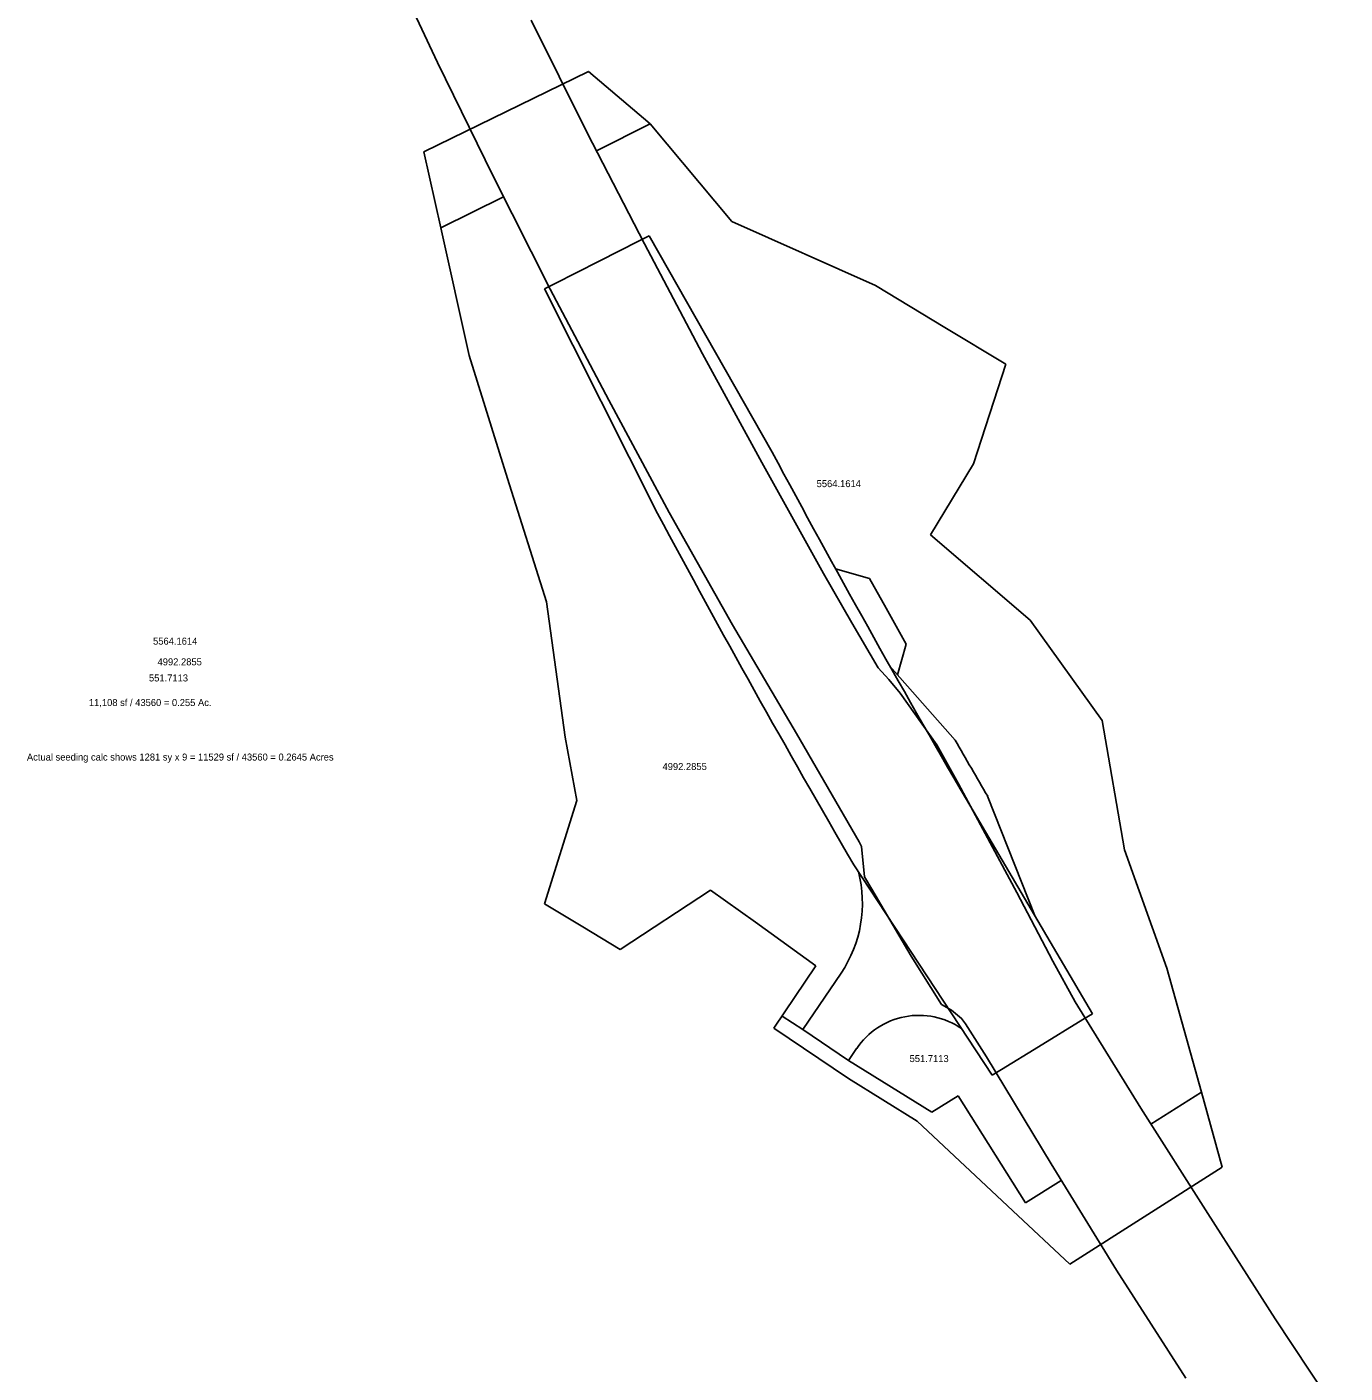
# Model space of a CAD drawing. Extents: x 2231639 to 2237084, y 681731 to 684172.
# Drawn here: x 2232533.2 to 2232796.6, y 683553.4 to 683822.5 of the extents above; entities that cross this region are included whole.
import ezdxf

# ---------------------------------------------------------------- set-up
doc = ezdxf.new("R2010")
doc.units = 0
for name, color, linetype in [('DT_P_Slope_Break_Line', 7, 'Continuous'), ('DT_X_Slope_Break_Line', 7, 'Continuous'), ('PV_P_Drive', 7, 'Continuous'), ('PV_P_Field_Drive', 7, 'Continuous'), ('PV_X_Shoulder_Aggregate', 7, 'Continuous'), ('RW_P_Const_Limits', 7, 'Continuous'), ('SH_Cut_Line', 7, 'Continuous'), ('SH_Named_Boundary', 7, 'Continuous'), ('VG_X_Cells', 7, 'Continuous')]:
    doc.layers.add(name, color=color, linetype=linetype)

msp = doc.modelspace()

# ---------------------------------------------------------------- linework, layer by layer
at = {"layer": 'DT_P_Slope_Break_Line'}
for p, q in [((2232684.08, 683624.78), (2232688.26, 683622.05)), ((2232697.39, 683615.9), (2232714.03, 683605.56)), ((2232719.31, 683608.8), (2232732.74, 683587.46))]:
    msp.add_line(p, q, dxfattribs=at)
at = {"layer": 'DT_X_Slope_Break_Line'}
for p, q in [((2232646.98, 683797.74), (2232657.72, 683803.08)), ((2232628.43, 683788.53), (2232615.86, 683782.29)), ((2232757.76, 683603.17), (2232767.89, 683609.53)), ((2232739.85, 683591.93), (2232732.74, 683587.46))]:
    msp.add_line(p, q, dxfattribs=at)
at = {"layer": 'PV_P_Drive'}
for p, q in [((2232718.66, 683679.94), (2232705.64, 683694.7)), ((2232725.17, 683668.69), (2232734.64, 683644.7)), ((2232695.88, 683633.36), (2232688.26, 683622.05)), ((2232697.39, 683615.9), (2232688.26, 683622.05)), ((2232698.99, 683618.29), (2232697.39, 683615.9))]:
    msp.add_line(p, q, dxfattribs=at)
for centre, radius, start, end in [((2234655.37, 684794.71), 2234.63, 209.92483, 210.25805), ((2232675.14, 683647.32), 25, 326.0548, 14.6337), ((2232711.44, 683609.91), 15, 55.5655, 146.0548)]:
    msp.add_arc(centre, radius, start, end, dxfattribs=at)
at = {"layer": 'PV_P_Field_Drive'}
for p, q in [((2232694.78, 683714.18), (2232701.55, 683712.24)), ((2232704.87, 683706.29), (2232701.55, 683712.24)), ((2232704.87, 683706.29), (2232708.89, 683699.08)), ((2232707.18, 683692.96), (2232708.89, 683699.08))]:
    msp.add_line(p, q, dxfattribs=at)
at = {"layer": 'PV_X_Shoulder_Aggregate'}
for points in [[(2232764.79, 683552.38), (2232750.93, 683574), (2232737.84, 683595.2), (2232724.91, 683616.61), (2232720.74, 683623.22), (2232719.95, 683624.29), (2232717.97, 683625.92), (2232715.97, 683627.1), (2232709.9, 683636.74), (2232702, 683650.15), (2232700.59, 683652.63), (2232699.93, 683658.67), (2232699.5, 683659.61), (2232686.97, 683681.28), (2232674.19, 683702.97), (2232661.51, 683725.43), (2232649.43, 683747.85), (2232637.74, 683770.04), (2232626.37, 683792.62), (2232615.25, 683815.35), (2232604.74, 683837.71)], [(2232796.61, 683543.1), (2232782.62, 683564.26), (2232769.18, 683585.29), (2232755.81, 683606.33), (2232742.64, 683627.63), (2232738.17, 683635.73), (2232731.01, 683649.47), (2232719.35, 683671.19), (2232715.01, 683678.98), (2232707.7, 683689.28), (2232705.39, 683692.01), (2232703.27, 683694.38), (2232698.03, 683703.34), (2232692.34, 683713.25), (2232680.01, 683735.42), (2232668.17, 683757.16), (2232656.62, 683779.14), (2232645.13, 683801.33), (2232633.92, 683823.81)]]:
    msp.add_lwpolyline(points, dxfattribs=at)
at = {"layer": 'RW_P_Const_Limits'}
for p, q in [((2232612.47, 683797.52), (2232645.41, 683813.6)), ((2232645.41, 683813.6), (2232657.72, 683803.08)), ((2232657.72, 683803.08), (2232674.02, 683783.59)), ((2232612.47, 683797.52), (2232615.86, 683782.29)), ((2232615.86, 683782.29), (2232621.52, 683756.8)), ((2232674.02, 683783.59), (2232702.78, 683770.78)), ((2232716.63, 683762.42), (2232702.78, 683770.78)), ((2232728.83, 683755.05), (2232716.63, 683762.42)), ((2232621.52, 683756.8), (2232629.18, 683732.19)), ((2232728.83, 683755.05), (2232722.31, 683735.13)), ((2232722.31, 683735.13), (2232713.78, 683720.93)), ((2232637.01, 683707.56), (2232629.18, 683732.19)), ((2232713.78, 683720.93), (2232733.65, 683703.88)), ((2232637.01, 683707.56), (2232640.74, 683680.53)), ((2232733.65, 683703.88), (2232748.04, 683683.87)), ((2232748.04, 683683.87), (2232752.51, 683657.99)), ((2232640.74, 683680.53), (2232643.06, 683667.83)), ((2232636.62, 683647.19), (2232643.06, 683667.83)), ((2232761, 683634.33), (2232752.51, 683657.99)), ((2232651.72, 683638.07), (2232669.81, 683649.95)), ((2232669.81, 683649.95), (2232678.75, 683643.51)), ((2232644.25, 683642.58), (2232636.62, 683647.19)), ((2232651.72, 683638.07), (2232644.25, 683642.58)), ((2232678.75, 683643.51), (2232690.83, 683634.81)), ((2232690.83, 683634.81), (2232682.44, 683622.35)), ((2232761, 683634.33), (2232767.89, 683609.53)), ((2232697.37, 683612.3), (2232682.44, 683622.35)), ((2232697.37, 683612.3), (2232711.1, 683603.77)), ((2232767.89, 683609.53), (2232772.04, 683594.58)), ((2232711.1, 683603.77), (2232730.2, 683585.87)), ((2232741.61, 683575.18), (2232772.04, 683594.58)), ((2232730.2, 683585.87), (2232741.61, 683575.18))]:
    msp.add_line(p, q, dxfattribs=at)
at = {"layer": 'SH_Cut_Line'}
for p, q in [((2232655.54, 683779.75), (2232657.51, 683780.75)), ((2232657.51, 683780.75), (2232682.11, 683737.49)), ((2232636.62, 683770.15), (2232638.58, 683771.15)), ((2232636.62, 683770.15), (2232659.19, 683725.22)), ((2232720.91, 683668.07), (2232746.1, 683625.21)), ((2232698.44, 683654.98), (2232726.06, 683612.93)), ((2232744.22, 683624.06), (2232746.1, 683625.21)), ((2232726.06, 683612.93), (2232727.94, 683614.08))]:
    msp.add_line(p, q, dxfattribs=at)
for radius in [2238.63, 2264.63]:
    msp.add_arc((2234655.37, 684794.71), radius, 208.18122, 210.21693, dxfattribs=at)
at = {"layer": 'SH_Named_Boundary'}
for p, q in [((2232647.53, 683775.69), (2232655.54, 683779.75)), ((2232638.58, 683771.15), (2232647.53, 683775.69)), ((2232735.32, 683618.6), (2232744.22, 683624.06)), ((2232727.94, 683614.08), (2232735.32, 683618.6))]:
    msp.add_line(p, q, dxfattribs=at)
at = {"layer": 'VG_X_Cells'}
msp.add_line((2232714.03, 683605.56), (2232719.31, 683608.8), dxfattribs=at)

# ---------------------------------------------------------------- texts
for s, p in [('5564.1614 ', (2232690.99, 683730.49)), ('5564.1614 ', (2232558.37, 683699.01)), ('4992.2855', (2232559.27, 683694.87)), ('551.7113', (2232557.55, 683691.65)), ('11,108 sf / 43560 = 0.255 Ac.', (2232545.54, 683686.73)), ('Actual seeding calc shows 1281 sy x 9 = 11529 sf / 43560 = 0.2645 Acres', (2232533.16, 683675.84)), ('4992.2855', (2232660.19, 683673.94)), ('551.7113', (2232709.57, 683615.57))]:
    msp.add_text(s, height=1.4, dxfattribs=at).set_placement(p)

doc.saveas('drawing.dxf')
